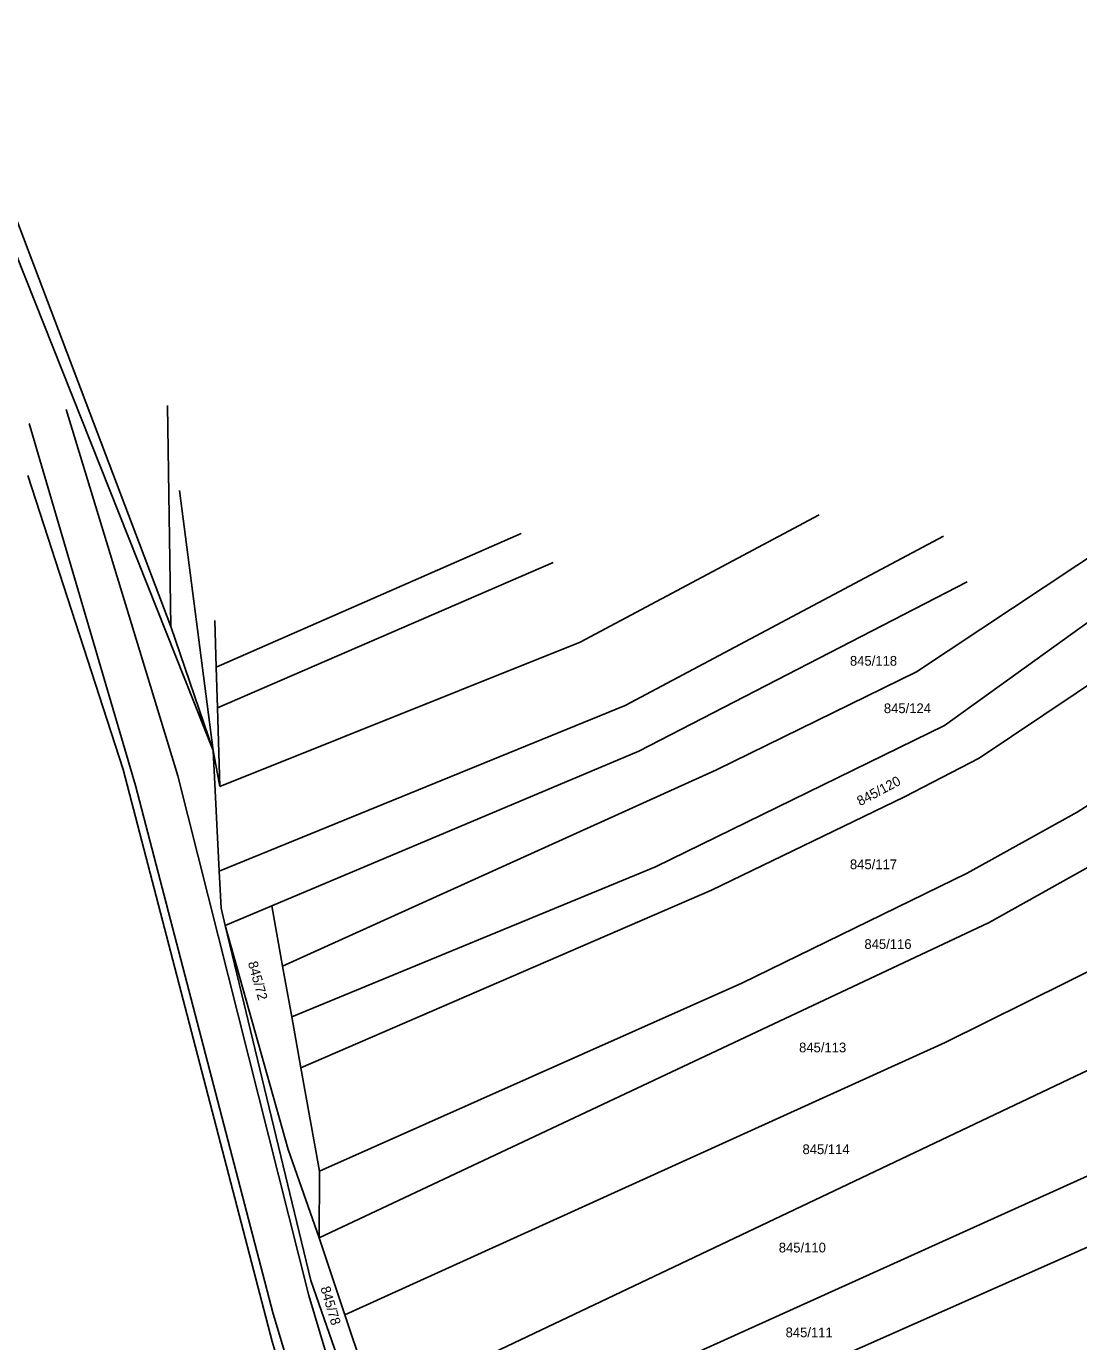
# Model space of a CAD drawing. Extents: x -563148 to -561712, y -1182311 to -1179502.
# Drawn here: x -562800.9 to -562639, y -1179704.6 to -1179502.2 of the extents above; entities that cross this region are included whole.
import ezdxf

# ---------------------------------------------------------------- set-up
doc = ezdxf.new("R2010")
doc.units = 0
for name, color, linetype in [('Vrstva 53', 7, 'Continuous'), ('Vrstva 55', 7, 'Continuous'), ('Vrstva 56', 7, 'Continuous'), ('Vrstva 57', 7, 'Continuous')]:
    doc.layers.add(name, color=color, linetype=linetype)

msp = doc.modelspace()

# ---------------------------------------------------------------- linework, layer by layer
at = {"layer": 'Vrstva 53'}
for p, q in [((-562800.68, -1179571.3), (-562786.03, -1179616.51)), ((-562786.03, -1179616.51), (-562763.1, -1179704.54)), ((-562763.1, -1179704.54), (-562738.93, -1179784.3))]:
    msp.add_line(p, q, dxfattribs=at)
at = {"layer": 'Vrstva 55'}
for p, q in [((-562816.46, -1179502.18), (-562772.16, -1179613.62)), ((-562810.75, -1179510.04), (-562778.68, -1179594.51)), ((-562663.96, -1179601.48), (-562582.04, -1179547.25)), ((-562659.65, -1179609.77), (-562583.42, -1179554.92)), ((-562779.2, -1179560.5), (-562778.68, -1179594.51)), ((-562777.36, -1179573.59), (-562772.16, -1179613.62)), ((-562715.68, -1179596.92), (-562678.95, -1179577.37)), ((-562724.8, -1179580.24), (-562771.69, -1179600.76)), ((-562708.77, -1179606.69), (-562659.79, -1179580.62)), ((-562719.85, -1179584.67), (-562771.5, -1179607.02)), ((-562706.69, -1179613.73), (-562656.15, -1179587.66)), ((-562771.91, -1179593.6), (-562771.69, -1179600.76)), ((-562621.24, -1179592.62), (-562654.33, -1179614.77)), ((-562772.16, -1179613.62), (-562778.68, -1179594.51)), ((-562771.13, -1179619.14), (-562715.68, -1179596.92)), ((-562771.69, -1179600.76), (-562771.5, -1179607.02)), ((-562694.71, -1179616.59), (-562663.96, -1179601.48)), ((-562639.21, -1179623.11), (-562605.08, -1179600.95)), ((-562771.5, -1179607.02), (-562771.13, -1179619.14)), ((-562708.77, -1179606.69), (-562771.23, -1179632.19)), ((-562704.1, -1179631.53), (-562659.65, -1179609.77)), ((-562772.16, -1179613.62), (-562771.23, -1179632.19)), ((-562771.13, -1179619.14), (-562772.16, -1179613.62)), ((-562706.69, -1179613.73), (-562763.17, -1179637.51)), ((-562654.33, -1179614.77), (-562665.79, -1179620.76)), ((-562652.76, -1179640.05), (-562607.16, -1179614.64)), ((-562761.5, -1179646.78), (-562694.71, -1179616.59)), ((-562665.79, -1179620.76), (-562695.49, -1179635.1)), ((-562656.15, -1179632.49), (-562639.21, -1179623.11)), ((-562704.1, -1179631.53), (-562760.09, -1179654.57)), ((-562771.23, -1179632.19), (-562770.95, -1179637.89)), ((-562690.8, -1179649.43), (-562656.15, -1179632.49)), ((-562758.67, -1179662.44), (-562695.49, -1179635.1)), ((-562770.95, -1179637.89), (-562770.31, -1179640.52)), ((-562763.17, -1179637.51), (-562770.31, -1179640.52)), ((-562763.17, -1179637.51), (-562761.5, -1179646.78)), ((-562659.54, -1179658.55), (-562617.47, -1179637.64)), ((-562755.84, -1179688.57), (-562652.76, -1179640.05)), ((-562770.31, -1179640.52), (-562757.15, -1179695.14)), ((-562770.31, -1179640.52), (-562760.62, -1179674.98)), ((-562761.5, -1179646.78), (-562760.09, -1179654.57)), ((-562755.79, -1179678.33), (-562690.8, -1179649.43)), ((-562760.09, -1179654.57), (-562758.67, -1179662.44)), ((-562747.06, -1179714.79), (-562625.32, -1179656.96)), ((-562751.93, -1179700.46), (-562659.54, -1179658.55)), ((-562758.67, -1179662.44), (-562755.79, -1179678.33)), ((-562755.84, -1179688.57), (-562760.62, -1179674.98)), ((-562743.41, -1179726.82), (-562630.14, -1179675.7)), ((-562755.84, -1179688.57), (-562755.79, -1179678.33)), ((-562751.93, -1179700.46), (-562755.84, -1179688.57)), ((-562740.58, -1179735.61), (-562633.32, -1179688.08)), ((-562757.15, -1179695.14), (-562727.13, -1179781.37)), ((-562747.06, -1179714.79), (-562751.93, -1179700.46))]:
    msp.add_line(p, q, dxfattribs=at)
at = {"layer": 'Vrstva 56'}
for p, q in [((-562794.8, -1179561.13), (-562777.59, -1179617.5)), ((-562800.5, -1179563.3), (-562784.13, -1179618.98)), ((-562777.59, -1179617.5), (-562757.45, -1179697.47)), ((-562784.13, -1179618.98), (-562762.95, -1179700.27)), ((-562757.45, -1179697.47), (-562732.11, -1179782.77)), ((-562762.95, -1179700.27), (-562737.47, -1179783.97))]:
    msp.add_line(p, q, dxfattribs=at)

# ---------------------------------------------------------------- texts
at = {"layer": 'Vrstva 57'}
for s, p in [('845/118', (-562674.19, -1179600.56)), ('845/124', (-562668.97, -1179607.86)), ('845/117', (-562674.19, -1179631.87)), ('845/116', (-562671.96, -1179644.14)), ('845/113', (-562682.01, -1179660.05)), ('845/114', (-562681.49, -1179675.71)), ('845/110', (-562685.14, -1179690.84)), ('845/111', (-562684.09, -1179703.89))]:
    msp.add_text(s, height=1.5, dxfattribs=at).set_placement(p)
for s, rotation, p in [('845/120', 27.9677, (-562672.62, -1179622.18)), ('845/72', 285.5162, (-562766.84, -1179646.26)), ('845/78', 286.5044, (-562755.68, -1179696.29))]:
    msp.add_text(s, height=1.5, rotation=rotation, dxfattribs=at).set_placement(p)

doc.saveas('drawing.dxf')
